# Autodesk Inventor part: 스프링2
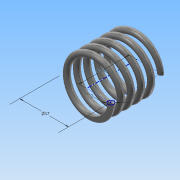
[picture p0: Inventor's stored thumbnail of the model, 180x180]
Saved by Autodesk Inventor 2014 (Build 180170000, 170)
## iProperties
Created: 2016-01
Part Number: 스프링2
Material: 강철, 탄소
Document SubType Name: Modeling
Designer: Administrator
Density: 7.87 g/cm^3
Appearance: 반연마
Mass: 6.44239 g
Surface Area: 16.6857 cm^2
Volume: 0.818602 cm^3
Author: Administrator
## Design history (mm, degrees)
sketch "스케치1"
  geometry: L1 (0, 0)-(8.5, 0); L2 (8.5, 0)-(8.5, 17.5); L3 (8.5, 17.5)-(0, 17.5); L4 (0, 17.5)-(0, 0); C1 r 1 at (8.5, 0)
  constraints: 8 end point, 2 parallel, 1 centre point, 1 coincident, 1 horizontal, 1 perpendicular
  dimensions: "d0" = 17 diameter of L2 L4; "d1" = 17.5 distance of L3.end L1.start (derived); "d2" = 2 diameter of C1
feature "코일1" sketch "스케치1" pitch "d3" = 10; turns "d5" = 5; dims "d4" = 17.5 (= d1), "d6" = 0, angle "d7" = 90 deg, angle "d8" = 90 deg, "d9" = 0, "d10" = 0
node "작업 평면1"
sketch "스케치2"
  geometry: L1 (-9.5, 0)-(-7.5, 0) reference; 1 further point
  constraints: 1 horizontal alignment
extrude "돌출1" cut sketch "스케치2" stored distance "d12" = 10; taper "d13" = 0 deg
node "작업 평면2"
sketch "스케치3"
  geometry: L1 (-7.5, 0)-(-9.5, 0) reference; 1 further point
  constraints: 1 horizontal alignment
extrude "돌출2" cut sketch "스케치3" stored distance "d15" = 10; taper "d16" = 0 deg
node "솔리드1"
node "절단 모서리 투영1"
node "절단 모서리 투영2"
other parameters: "d11" = 0, "d14" = 17.5 (= d1)
